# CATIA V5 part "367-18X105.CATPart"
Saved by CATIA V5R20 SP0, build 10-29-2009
Part number: 367-18X105
Definition: NONE
Nomenclature: 367-18X105
Source: Unknown
Description: 367-18X105
Bounding box of the stored display mesh (mm): x 0 to 105, y -14 to 14, z -14 to 14
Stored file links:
  C:\Users\Utente\Desktop\IO LAVORO\3D X SITO CF\X SITO\PLASTICA\3D files 367\367-18X105.CATPart
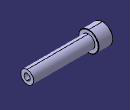
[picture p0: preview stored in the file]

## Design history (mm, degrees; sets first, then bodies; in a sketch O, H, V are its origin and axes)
Body1 "367-18X105" (main body)
  Solid1: solid without history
